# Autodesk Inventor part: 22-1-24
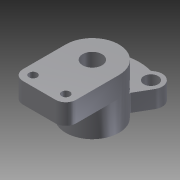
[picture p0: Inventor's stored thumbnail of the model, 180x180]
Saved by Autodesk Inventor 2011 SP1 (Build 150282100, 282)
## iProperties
Created: 2014-01
Part Number: 22-1-24
Document SubType Name: Modeling
Designer: Administrator
Density: 1 g/cm^3
Author: Administrator
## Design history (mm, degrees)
sketch "草图1"
  geometry: C1 r 26 at (0, 0); 1 further point
  constraints: 1 centre point, 1 coincident
  dimensions: "d0" = 52 diameter of C1
extrude "拉伸1" new body sketch "草图1" distance "d1" = 49; taper "d2" = 0 deg
hole "Hole1" diameter "d5" = 19; stored, may be unused: countersink angle "d9" = 90 deg, drill point angle "d11" = 0 deg; dims "d3" = 10, "d4" = 10, "d6" = 6, "d7" = 29, "d8" = 14, "d10" = 8
sketch "草图2"
  geometry: L1 (-16, -52)-(16, -52); L2 (26, -42)-(26, 0); L3 (-26, 0)-(-26, -42); C1 r 9.5 at (0, 0) reference; C2 r 26 at (0, 0) reference; A1 r 10 centre (-16, -42) between (-26, -42) and (-16, -52); A2 r 10 centre (16, -42) between (16, -52) and (26, -42); 2 further points
  constraints: 6 end point, 6 tangent, 4 point on circle, 2 centre point, 2 point on line, 1 coincident, 1 horizontal, 1 parallel, 1 perpendicular
  dimensions: "d12" = 52 distance of L2.end L3.start; "d13" = 52 distance of L3.start point (-26, -52); "d14" = 10 radius of A1; "d15" = 10 radius of A2
extrude "拉伸2" join sketch "草图2" distance "d17" = 20; taper "d18" = 0 deg
hole "Hole2" diameter "d21" = 8; stored, may be unused: countersink angle "d25" = 90 deg, drill point angle "d27" = 118 deg; dims "d19" = 10, "d20" = 10, "d22" = 6, "d23" = 12, "d24" = 7, "d26" = 8
mirror "镜像1"
node "工作平面1"
sketch "草图3"
  geometry: L1 (30.526, 30.873)-(21.305, 14.902); L2 (-30.526, 30.873)-(-21.305, 14.902); A1 r 46 centre (0, 0) between (12.094, 44.382) and (-12.094, 44.382); A2 r 11 centre (21, 36.373) between (30.526, 30.873) and (13.909, 44.782); A3 r 11 centre (-21, 36.373) between (-13.909, 44.782) and (-30.526, 30.873); A4 r 2 centre (12.62, 46.311) between (12.094, 44.382) and (13.909, 44.782); A5 r 2 centre (-12.62, 46.311) between (-13.909, 44.782) and (-12.094, 44.382); A6 r 26 centre (0, 0) between (21.305, 14.902) and (-21.305, 14.902); 2 further points
  constraints: 12 point on circle, 6 centre point, 5 tangent, 4 end point, 2 coincident, 2 other
  dimensions: "d32" = 22 diameter of A2; "d33" = 2 radius of A4; "d34" = 2 radius of A5
extrude "拉伸3" join sketch "草图3" distance "d36" = 17; taper "d37" = 0 deg
fillet "圆角1" dims "d38" = 2
hole "Hole3" diameter "d41" = 14; stored, may be unused: countersink angle "d45" = 90 deg, drill point angle "d47" = 118 deg; dims "d39" = 10, "d40" = 10, "d42" = 6, "d43" = 12, "d44" = 7, "d46" = 8
mirror "镜像2"
node "实体1"
other parameters: "d28" = -7
